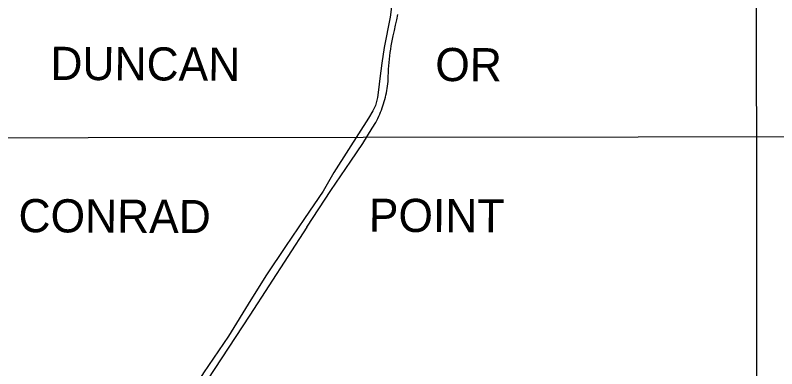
# Model space of a CAD drawing. Extents: x 3297735 to 3335592, y 670436 to 695807.
# Drawn here: x 3319645 to 3322973, y 677846 to 679392 of the extents above; entities that cross this region are included whole.
import ezdxf

# ---------------------------------------------------------------- set-up
doc = ezdxf.new("R2010")
doc.units = 0
for name, color, linetype in [('V-DTCH-CNTR', 7, 'Continuous'), ('V-GRID-MAJR', 7, 'Continuous'), ('V-TOPO-GNAM-IDEN', 7, 'Continuous'), ('V-TOPO-SHOR', 7, 'Continuous')]:
    doc.layers.add(name, color=color, linetype=linetype)

msp = doc.modelspace()

# ---------------------------------------------------------------- linework, layer by layer
at = {"layer": 'V-DTCH-CNTR'}
for points in [[(3320920, 678465.6), (3321023.8, 678625), (3321111.9, 678754.5), (3321164.5, 678831.3), (3321205.7, 678898.2), (3321210.9, 678906.6), (3321215.8, 678915.1), (3321220.6, 678923.7), (3321225.2, 678932.5), (3321229.6, 678941.3), (3321233.8, 678950.2), (3321237.8, 678959.2), (3321241.7, 678968.3), (3321245.3, 678977.4), (3321248.8, 678986.6), (3321252, 678996), (3321255.1, 679005.3), (3321257.9, 679014.8), (3321260.6, 679024.2), (3321263.1, 679033.8), (3321265.3, 679043.4), (3321267.4, 679053), (3321269.2, 679062.7), (3321270.8, 679072.4), (3321272.3, 679082.2), (3321273.5, 679092), (3321274.5, 679101.8), (3321275.3, 679111.6), (3321275.6, 679126.4), (3321276.1, 679141.1), (3321276.8, 679155.9), (3321277.8, 679170.6), (3321279, 679185.4), (3321280.4, 679200.1), (3321282, 679214.8), (3321283.9, 679229.4), (3321286, 679244.1), (3321288.3, 679258.7), (3321290.8, 679273.2), (3321293.6, 679287.7), (3321296.6, 679302.2), (3321302, 679325.6), (3321307.3, 679349.1), (3321312.3, 679372.6), (3321317.2, 679396.2)], [(3320920, 678465.6), (3320669.8, 678080.3), (3320422.3, 677703.2), (3320243.3, 677422.1), (3320028, 677087.5), (3319853.1, 676804.9), (3319843.2, 676770.5), (3319843.1, 676763.6), (3319845.8, 676751.2), (3319936, 676656.6), (3320049.4, 676535.7), (3320110.7, 676453.8), (3320114.7, 676439.9), (3320121.5, 676421.9), (3320121.4, 676413.7), (3320116.1, 676379), (3320094.3, 676329.5), (3320006.9, 676115.2), (3319885.8, 675833.3)]]:
    msp.add_lwpolyline(points, dxfattribs=at)
at = {"layer": 'V-GRID-MAJR'}
for points in [[(3322888.3, 675833.4), (3322887.1, 676864.4), (3322885.2, 678460.2), (3322882.7, 680598.7), (3322880.2, 682800.9), (3322878.2, 684524.6), (3322875.8, 686599.5), (3322873.1, 688865.9), (3322871.2, 690525.6), (3322869.2, 692280.9), (3322867.5, 693717.1), (3322867.1, 694017.9)], [(3301860.2, 678842.7), (3303311.9, 678843.6), (3306791, 678845.9), (3310174.4, 678848.5), (3313813, 678851.6), (3318760.4, 678856.5), (3322367.1, 678860.5), (3326388.7, 678865.3), (3330442.3, 678870.6), (3332389.2, 678873.4), (3333397.1, 678874.8)]]:
    msp.add_lwpolyline(points, dxfattribs=at)
at = {"layer": 'V-TOPO-SHOR'}
for points in [[(3321343.9, 679897.5), (3321337.6, 679790.1), (3321319.1, 679642.9), (3321300, 679512.7), (3321283, 679383.3), (3321256.7, 679251.7), (3321246.8, 679182.7), (3321239, 679115.8), (3321232.6, 679066), (3321227.7, 679032.6), (3321219.1, 678997.7), (3321208.5, 678973.6), (3321188.6, 678942.3), (3321101.2, 678805.7), (3321037.2, 678703.9), (3320990.3, 678622.8), (3320909.3, 678503.3)], [(3320909.3, 678503.3), (3320825.9, 678380.2), (3320743.8, 678256.4), (3320675.2, 678147.4), (3320576.9, 677988.5), (3320468.7, 677828.1), (3320378.4, 677682.2), (3320264.6, 677508), (3320166.3, 677356.2), (3320074.1, 677209.1), (3319980.7, 677067.9), (3319876.7, 676895.6), (3319768.5, 676734.4), (3319734.9, 676689.9)]]:
    msp.add_lwpolyline(points, dxfattribs=at)

# ---------------------------------------------------------------- texts
at = {"layer": 'V-TOPO-GNAM-IDEN'}
for s, p in [('DUNCAN', (3319798.8, 679109.7)), ('OR', (3321480.5, 679104.6)), ('CONRAD', (3319659.4, 678443.5)), ('POINT', (3321190.2, 678445.3))]:
    msp.add_text(s, height=145, rotation=359.6879, dxfattribs=at).set_placement(p)

doc.saveas('drawing.dxf')
